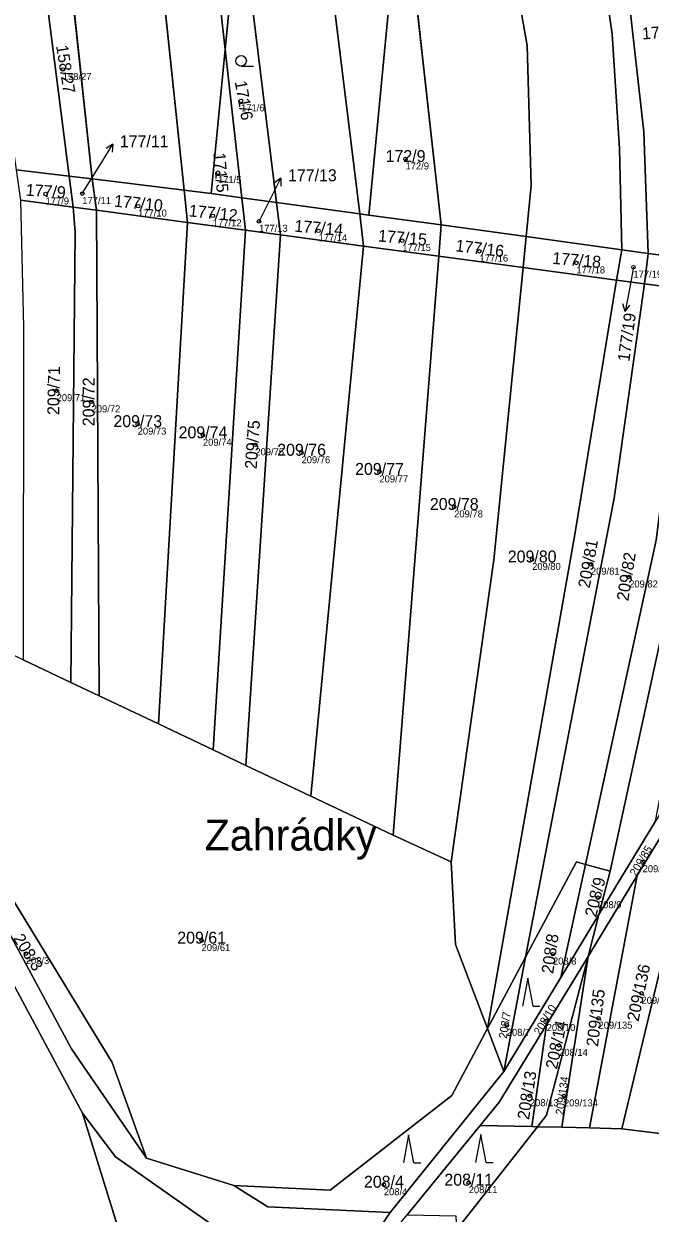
# Model space of a CAD drawing. Extents: x -603967 to -594699, y -1179315 to -1165625.
# Drawn here: x -597618.1 to -597528.8, y -1172909.2 to -1172739.7 of the extents above; entities that cross this region are included whole.
import ezdxf

# ---------------------------------------------------------------- set-up
doc = ezdxf.new("R2010")
doc.units = 0
for name, color, linetype in [('Definiční body', 7, 'Continuous'), ('Hranice parcel', 7, 'Continuous'), ('Parcelní čísla', 7, 'Continuous'), ('Polygon parcely', 7, 'Continuous'), ('Pop  PČ popisy', 7, 'Continuous'), ('Značky kultur', 7, 'Continuous')]:
    doc.layers.add(name, color=color, linetype=linetype)

msp = doc.modelspace()

# ---------------------------------------------------------------- linework, layer by layer
at = {"layer": 'Definiční body'}
for centre in [(-597612.53, -1172746.22994), (-597587.11, -1172750.68994), (-597563.66, -1172758.97994), (-597590.4, -1172760.92994), (-597614.99, -1172763.96994), (-597609.75, -1172763.90994), (-597601.79, -1172765.68994), (-597591.13, -1172767.07994), (-597584.55, -1172767.85994), (-597576.07, -1172769.19994), (-597564.13, -1172770.59994), (-597553.12, -1172772.11994), (-597539.29, -1172773.78994), (-597531.16, -1172774.38994), (-597613.41, -1172791.98994), (-597608.42, -1172793.57994), (-597601.85, -1172796.74994), (-597592.55, -1172798.33994), (-597585.07, -1172799.69994), (-597578.49, -1172800.82994), (-597567.38, -1172803.55994), (-597556.72, -1172808.54994), (-597545.61, -1172816.02994), (-597537.22, -1172816.70994), (-597531.77, -1172818.52994), (-597529.85, -1172859.09994), (-597536.21, -1172864.21994), (-597592.74, -1172870.32994), (-597617.81, -1172872.18994), (-597542.63, -1172872.24994), (-597530.01, -1172877.83994), (-597536.14, -1172881.38994), (-597549.22, -1172882.40994), (-597543.53, -1172881.72994), (-597541.76, -1172885.25994), (-597545.93, -1172892.42994), (-597541.06, -1172892.45994), (-597566.75, -1172905.10994), (-597554.65, -1172904.81994)]:
    msp.add_circle(centre, 0.25, dxfattribs=at)
at = {"layer": 'Hranice parcel'}
for p, q in [((-597570.19, -1172766.78), (-597579.38, -1172691.97)), ((-597589.37, -1172743.38), (-597594.18, -1172700.51)), ((-597595.22, -1172763.42), (-597601.41, -1172704.69)), ((-597613.71, -1172712.02), (-597608.32, -1172761.82)), ((-597611.6, -1172761.42), (-597617.67, -1172714.08)), ((-597568.89, -1172766.96), (-597564.18, -1172717.82)), ((-597558.57, -1172768.37), (-597564.18, -1172717.82)), ((-597589.37, -1172743.38), (-597587.32, -1172722.3)), ((-597582.05, -1172765.17), (-597587.32, -1172722.3)), ((-597591.36, -1172763.89), (-597589.37, -1172743.38)), ((-597587, -1172764.49), (-597589.37, -1172743.38)), ((-597619.16, -1172760.5), (-597611.6, -1172761.42)), ((-597611.03, -1172765.83), (-597611.6, -1172761.42)), ((-597611.6, -1172761.42), (-597608.32, -1172761.82)), ((-597608.32, -1172761.82), (-597607.73, -1172766.27)), ((-597608.32, -1172761.82), (-597595.22, -1172763.42)), ((-597594.74, -1172768.01), (-597595.22, -1172763.42)), ((-597595.22, -1172763.42), (-597591.36, -1172763.89)), ((-597591.36, -1172763.89), (-597587, -1172764.49)), ((-597618.55, -1172764.82), (-597611.03, -1172765.83)), ((-597611.03, -1172765.83), (-597607.73, -1172766.27)), ((-597587, -1172764.49), (-597582.05, -1172765.17)), ((-597586.48, -1172769.12), (-597587, -1172764.49)), ((-597582.05, -1172765.17), (-597570.19, -1172766.78)), ((-597581.48, -1172769.79), (-597582.05, -1172765.17)), ((-597607.73, -1172766.27), (-597594.74, -1172768.01)), ((-597607.36, -1172835.44), (-597607.73, -1172766.27)), ((-597570.19, -1172766.78), (-597568.89, -1172766.96)), ((-597569.63, -1172771.38), (-597570.19, -1172766.78)), ((-597568.89, -1172766.96), (-597558.57, -1172768.37)), ((-597598.88, -1172839.45), (-597594.74, -1172768.01)), ((-597594.74, -1172768.01), (-597586.48, -1172769.12)), ((-597591.11, -1172843.13), (-597586.48, -1172769.12)), ((-597586.48, -1172769.12), (-597581.48, -1172769.79)), ((-597558.92, -1172772.82), (-597558.57, -1172768.37)), ((-597558.57, -1172768.37), (-597546.46, -1172770.03)), ((-597586.41, -1172845.36), (-597581.48, -1172769.79)), ((-597581.48, -1172769.79), (-597569.63, -1172771.38)), ((-597546.89, -1172774.43), (-597546.46, -1172770.03)), ((-597546.46, -1172770.03), (-597532.83, -1172771.9)), ((-597577.14, -1172849.75), (-597569.63, -1172771.38)), ((-597569.63, -1172771.38), (-597558.92, -1172772.82)), ((-597533.55, -1172776.22), (-597532.83, -1172771.9)), ((-597532.83, -1172771.9), (-597529.06, -1172772.42)), ((-597529.57, -1172776.75), (-597529.06, -1172772.42)), ((-597529.06, -1172772.42), (-597522.87, -1172773.26)), ((-597565.41, -1172855.3), (-597558.92, -1172772.82)), ((-597558.92, -1172772.82), (-597546.89, -1172774.43)), ((-597546.89, -1172774.43), (-597533.55, -1172776.22)), ((-597533.55, -1172776.22), (-597529.57, -1172776.75)), ((-597529.57, -1172776.75), (-597523.41, -1172777.58)), ((-597611.38, -1172833.54), (-597618.17, -1172830.33)), ((-597607.36, -1172835.44), (-597611.38, -1172833.54)), ((-597598.88, -1172839.45), (-597607.36, -1172835.44)), ((-597591.11, -1172843.13), (-597598.88, -1172839.45)), ((-597586.41, -1172845.36), (-597591.11, -1172843.13)), ((-597577.14, -1172849.75), (-597586.41, -1172845.36)), ((-597530.61, -1172861.05), (-597520.68, -1172844.76)), ((-597565.41, -1172855.3), (-597577.14, -1172849.75)), ((-597536.07, -1172866.61), (-597528.03, -1172853.32)), ((-597557.14, -1172859.11), (-597565.41, -1172855.3)), ((-597541.5, -1172875.58), (-597537.99, -1172859.47)), ((-597534.46, -1172860.45), (-597537.99, -1172859.47)), ((-597536.07, -1172866.61), (-597534.46, -1172860.45)), ((-597537.63, -1172872.57), (-597530.61, -1172861.05)), ((-597537.43, -1172897.02), (-597530.61, -1172861.05)), ((-597541.5, -1172875.58), (-597536.07, -1172866.61)), ((-597537.63, -1172872.57), (-597536.07, -1172866.61)), ((-597546.53, -1172872.69), (-597551.96, -1172882.86)), ((-597549.62, -1172888.99), (-597546.53, -1172872.69)), ((-597543.57, -1172882.32), (-597537.63, -1172872.57)), ((-597541.36, -1172896.93), (-597537.63, -1172872.57)), ((-597549.62, -1172888.99), (-597541.5, -1172875.58)), ((-597549.62, -1172888.99), (-597551.96, -1172882.86)), ((-597545.64, -1172896.83), (-597543.57, -1172882.32)), ((-597565.86, -1172909.04), (-597549.62, -1172888.99)), ((-597609.7, -1172894.89), (-597599.63, -1172927.39)), ((-597563.42, -1172909.38), (-597553.01, -1172896.66)), ((-597556.37, -1172911.53), (-597544.84, -1172896.85)), ((-597545.64, -1172896.83), (-597553.01, -1172896.66)), ((-597544.84, -1172896.85), (-597545.64, -1172896.83)), ((-597541.36, -1172896.93), (-597544.84, -1172896.85)), ((-597537.43, -1172897.02), (-597541.36, -1172896.93)), ((-597532.79, -1172897.13), (-597537.43, -1172897.02)), ((-597524.24, -1172898.2), (-597532.79, -1172897.13)), ((-597588.14, -1172905.22), (-597600.57, -1172901.34)), ((-597571.27, -1172916.99), (-597565.86, -1172909.04))]:
    msp.add_line(p, q, dxfattribs=at)
for points in [[(-597529.06, -1172772.42), (-597529.67, -1172755.13), (-597533.92, -1172717.49), (-597537.73, -1172693.52), (-597542.15, -1172671.52)], [(-597532.83, -1172771.9), (-597533.15, -1172757.5), (-597534.21, -1172741.19), (-597538.43, -1172711.6), (-597545.49, -1172673.32)], [(-597546.46, -1172770.03), (-597545.76, -1172762.74), (-597546.31, -1172742.82), (-597555.17, -1172693.06), (-597557.04, -1172679.77)], [(-597611.38, -1172833.54), (-597610.76, -1172769.39), (-597611.03, -1172765.83)], [(-597557.14, -1172859.11), (-597551.05, -1172816.06), (-597546.89, -1172774.43)], [(-597551.96, -1172882.86), (-597539.49, -1172812.18), (-597533.55, -1172776.22)], [(-597546.53, -1172872.69), (-597533.9, -1172807.29), (-597529.57, -1172776.75)], [(-597537.99, -1172859.47), (-597527.91, -1172813.28), (-597523.41, -1172777.58)], [(-597534.46, -1172860.45), (-597523.22, -1172808.61), (-597518.36, -1172778.25)], [(-597600.57, -1172901.34), (-597605.51, -1172887.71), (-597645.57, -1172822.13), (-597649.68, -1172826.73)], [(-597650.17, -1172830.11), (-597634.48, -1172842.73), (-597611.3, -1172885.74), (-597600.57, -1172901.34)], [(-597650.63, -1172833.28), (-597638.01, -1172842.26), (-597609.7, -1172894.89)], [(-597532.79, -1172897.13), (-597523.17, -1172857.04), (-597520.68, -1172844.76)], [(-597551.96, -1172882.86), (-597556.53, -1172870.87), (-597557.14, -1172859.11)], [(-597537.99, -1172859.47), (-597539.27, -1172859.11), (-597546.53, -1172872.69)], [(-597544.84, -1172896.85), (-597543.55, -1172895.2), (-597537.63, -1172872.57)], [(-597551.96, -1172882.86), (-597557.05, -1172892.39), (-597574.38, -1172905.89), (-597588.14, -1172905.22)], [(-597553.01, -1172896.66), (-597550.3, -1172893.35), (-597543.57, -1172882.32)], [(-597578.6, -1172919.68), (-597605.03, -1172901.12), (-597609.7, -1172894.89)], [(-597588.14, -1172905.22), (-597583.31, -1172908.26), (-597565.86, -1172909.04)]]:
    msp.add_lwpolyline(points, dxfattribs=at)
at = {"layer": 'Polygon parcely'}
for points in [[(-597534.3, -1172667.32), (-597542.15, -1172671.52), (-597537.73, -1172693.52), (-597533.92, -1172717.49), (-597529.67, -1172755.13), (-597529.06, -1172772.42), (-597522.87, -1172773.26), (-597522.28, -1172768.57), (-597522.52, -1172739.46), (-597526.98, -1172708.75)], [(-597542.15, -1172671.52), (-597545.49, -1172673.32), (-597538.43, -1172711.6), (-597534.21, -1172741.19), (-597533.15, -1172757.5), (-597532.83, -1172771.9), (-597529.06, -1172772.42), (-597529.67, -1172755.13), (-597533.92, -1172717.49), (-597537.73, -1172693.52)], [(-597545.49, -1172673.32), (-597557.04, -1172679.77), (-597555.17, -1172693.06), (-597546.31, -1172742.82), (-597545.76, -1172762.74), (-597546.46, -1172770.03), (-597532.83, -1172771.9), (-597533.15, -1172757.5), (-597534.21, -1172741.19), (-597538.43, -1172711.6)], [(-597557.04, -1172679.77), (-597560.72, -1172681.78), (-597564.18, -1172717.82), (-597558.57, -1172768.37), (-597546.46, -1172770.03), (-597545.76, -1172762.74), (-597546.31, -1172742.82), (-597555.17, -1172693.06)], [(-597570.19, -1172766.78), (-597568.89, -1172766.96), (-597564.18, -1172717.82), (-597567.75, -1172685.61), (-597579.38, -1172691.97)], [(-597579.38, -1172691.97), (-597584.67, -1172695.02), (-597587.32, -1172722.3), (-597582.05, -1172765.17), (-597570.19, -1172766.78)], [(-597589.37, -1172743.38), (-597587.32, -1172722.3), (-597590.28, -1172698.26), (-597594.18, -1172700.51)], [(-597594.18, -1172700.51), (-597601.41, -1172704.69), (-597595.22, -1172763.42), (-597591.36, -1172763.89), (-597589.37, -1172743.38)], [(-597595.22, -1172763.42), (-597601.41, -1172704.69), (-597613.71, -1172712.02), (-597608.32, -1172761.82)], [(-597611.6, -1172761.42), (-597608.32, -1172761.82), (-597613.71, -1172712.02), (-597617.67, -1172714.08)], [(-597617.67, -1172714.08), (-597625.15, -1172718.4), (-597619.16, -1172760.5), (-597611.6, -1172761.42)], [(-597558.57, -1172768.37), (-597564.18, -1172717.82), (-597568.89, -1172766.96)], [(-597582.05, -1172765.17), (-597587.32, -1172722.3), (-597589.37, -1172743.38), (-597587, -1172764.49)], [(-597587, -1172764.49), (-597589.37, -1172743.38), (-597591.36, -1172763.89)], [(-597611.03, -1172765.83), (-597611.6, -1172761.42), (-597619.16, -1172760.5), (-597618.55, -1172764.82)], [(-597611.03, -1172765.83), (-597607.73, -1172766.27), (-597608.32, -1172761.82), (-597611.6, -1172761.42)], [(-597594.74, -1172768.01), (-597595.22, -1172763.42), (-597608.32, -1172761.82), (-597607.73, -1172766.27)], [(-597586.48, -1172769.12), (-597587, -1172764.49), (-597591.36, -1172763.89), (-597595.22, -1172763.42), (-597594.74, -1172768.01)], [(-597611.38, -1172833.54), (-597610.76, -1172769.39), (-597611.03, -1172765.83), (-597618.55, -1172764.82), (-597618.13, -1172782.99), (-597618.17, -1172830.33)], [(-597607.36, -1172835.44), (-597607.73, -1172766.27), (-597611.03, -1172765.83), (-597610.76, -1172769.39), (-597611.38, -1172833.54)], [(-597581.48, -1172769.79), (-597582.05, -1172765.17), (-597587, -1172764.49), (-597586.48, -1172769.12)], [(-597569.63, -1172771.38), (-597570.19, -1172766.78), (-597582.05, -1172765.17), (-597581.48, -1172769.79)], [(-597598.88, -1172839.45), (-597594.74, -1172768.01), (-597607.73, -1172766.27), (-597607.36, -1172835.44)], [(-597558.92, -1172772.82), (-597558.57, -1172768.37), (-597568.89, -1172766.96), (-597570.19, -1172766.78), (-597569.63, -1172771.38)], [(-597591.11, -1172843.13), (-597586.48, -1172769.12), (-597594.74, -1172768.01), (-597598.88, -1172839.45)], [(-597586.41, -1172845.36), (-597581.48, -1172769.79), (-597586.48, -1172769.12), (-597591.11, -1172843.13)], [(-597546.89, -1172774.43), (-597546.46, -1172770.03), (-597558.57, -1172768.37), (-597558.92, -1172772.82)], [(-597577.14, -1172849.75), (-597569.63, -1172771.38), (-597581.48, -1172769.79), (-597586.41, -1172845.36)], [(-597546.89, -1172774.43), (-597533.55, -1172776.22), (-597532.83, -1172771.9), (-597546.46, -1172770.03)], [(-597565.41, -1172855.3), (-597558.92, -1172772.82), (-597569.63, -1172771.38), (-597577.14, -1172849.75)], [(-597529.06, -1172772.42), (-597532.83, -1172771.9), (-597533.55, -1172776.22), (-597529.57, -1172776.75)], [(-597523.41, -1172777.58), (-597522.87, -1172773.26), (-597529.06, -1172772.42), (-597529.57, -1172776.75)], [(-597551.05, -1172816.06), (-597546.89, -1172774.43), (-597558.92, -1172772.82), (-597565.41, -1172855.3), (-597557.14, -1172859.11)], [(-597539.49, -1172812.18), (-597533.55, -1172776.22), (-597546.89, -1172774.43), (-597551.05, -1172816.06), (-597557.14, -1172859.11), (-597556.53, -1172870.87), (-597551.96, -1172882.86)], [(-597529.57, -1172776.75), (-597533.55, -1172776.22), (-597539.49, -1172812.18), (-597551.96, -1172882.86), (-597546.53, -1172872.69), (-597533.9, -1172807.29)], [(-597527.91, -1172813.28), (-597523.41, -1172777.58), (-597529.57, -1172776.75), (-597533.9, -1172807.29), (-597546.53, -1172872.69), (-597539.27, -1172859.11), (-597537.99, -1172859.47)], [(-597534.46, -1172860.45), (-597523.22, -1172808.61), (-597518.36, -1172778.25), (-597523.41, -1172777.58), (-597527.91, -1172813.28), (-597537.99, -1172859.47)], [(-597528.03, -1172853.32), (-597520.99, -1172816.83), (-597514.19, -1172778.81), (-597518.36, -1172778.25), (-597523.22, -1172808.61), (-597534.46, -1172860.45), (-597536.07, -1172866.61)], [(-597637.45, -1172821.21), (-597641.95, -1172819.08), (-597648.14, -1172816.15), (-597649.18, -1172823.26), (-597649.68, -1172826.73), (-597645.57, -1172822.13), (-597605.51, -1172887.71), (-597600.57, -1172901.34), (-597588.14, -1172905.22), (-597574.38, -1172905.89), (-597557.05, -1172892.39), (-597551.96, -1172882.86), (-597556.53, -1172870.87), (-597557.14, -1172859.11), (-597565.41, -1172855.3), (-597577.14, -1172849.75), (-597586.41, -1172845.36), (-597591.11, -1172843.13), (-597598.88, -1172839.45), (-597607.36, -1172835.44), (-597611.38, -1172833.54), (-597618.17, -1172830.33), (-597627.48, -1172825.93)], [(-597645.57, -1172822.13), (-597649.68, -1172826.73), (-597650.17, -1172830.11), (-597634.48, -1172842.73), (-597611.3, -1172885.74), (-597600.57, -1172901.34), (-597605.51, -1172887.71)], [(-597650.63, -1172833.28), (-597638.01, -1172842.26), (-597609.7, -1172894.89), (-597605.03, -1172901.12), (-597578.6, -1172919.68), (-597571.27, -1172916.99), (-597565.86, -1172909.04), (-597583.31, -1172908.26), (-597588.14, -1172905.22), (-597600.57, -1172901.34), (-597611.3, -1172885.74), (-597634.48, -1172842.73), (-597650.17, -1172830.11), (-597650.19, -1172830.23)], [(-597634.82, -1172941.98), (-597599.63, -1172927.39), (-597609.7, -1172894.89), (-597638.01, -1172842.26), (-597650.63, -1172833.28), (-597650.98, -1172835.68), (-597651.92, -1172842.12), (-597652.27, -1172844.56), (-597652.75, -1172847.85), (-597653.74, -1172854.63), (-597655.06, -1172863.69), (-597656.63, -1172874.7), (-597658.05, -1172886.36), (-597659.6, -1172899.14), (-597661.01, -1172910.7), (-597662.27, -1172921.05), (-597662.44, -1172931.04), (-597662.54, -1172938.91), (-597662.54, -1172947.84), (-597662.5, -1172951.67)], [(-597520.68, -1172844.76), (-597519.7, -1172841.11), (-597519.47, -1172839.39), (-597528.03, -1172853.32), (-597536.07, -1172866.61), (-597537.63, -1172872.57), (-597530.61, -1172861.05)], [(-597503.54, -1172844.31), (-597519.7, -1172841.11), (-597520.68, -1172844.76), (-597523.17, -1172857.04), (-597532.79, -1172897.13), (-597524.24, -1172898.2), (-597523.27, -1172895.86), (-597518, -1172883.14), (-597514.32, -1172874.25), (-597512.34, -1172869.47), (-597512.13, -1172868.86), (-597507.98, -1172856.67)], [(-597523.17, -1172857.04), (-597520.68, -1172844.76), (-597530.61, -1172861.05), (-597537.43, -1172897.02), (-597532.79, -1172897.13)], [(-597541.5, -1172875.58), (-597537.99, -1172859.47), (-597539.27, -1172859.11), (-597546.53, -1172872.69), (-597549.62, -1172888.99)], [(-597534.46, -1172860.45), (-597537.99, -1172859.47), (-597541.5, -1172875.58), (-597536.07, -1172866.61)], [(-597537.43, -1172897.02), (-597530.61, -1172861.05), (-597537.63, -1172872.57), (-597541.36, -1172896.93)], [(-597571.27, -1172916.99), (-597568.95, -1172916.14), (-597563.42, -1172909.38), (-597553.01, -1172896.66), (-597550.3, -1172893.35), (-597543.57, -1172882.32), (-597537.63, -1172872.57), (-597536.07, -1172866.61), (-597541.5, -1172875.58), (-597549.62, -1172888.99), (-597565.86, -1172909.04)], [(-597549.62, -1172888.99), (-597546.53, -1172872.69), (-597551.96, -1172882.86)], [(-597543.55, -1172895.2), (-597537.63, -1172872.57), (-597543.57, -1172882.32), (-597545.64, -1172896.83), (-597544.84, -1172896.85)], [(-597541.36, -1172896.93), (-597537.63, -1172872.57), (-597543.55, -1172895.2), (-597544.84, -1172896.85)], [(-597574.38, -1172905.89), (-597588.14, -1172905.22), (-597583.31, -1172908.26), (-597565.86, -1172909.04), (-597549.62, -1172888.99), (-597551.96, -1172882.86), (-597557.05, -1172892.39)], [(-597545.64, -1172896.83), (-597543.57, -1172882.32), (-597550.3, -1172893.35), (-597553.01, -1172896.66)], [(-597578.6, -1172919.68), (-597605.03, -1172901.12), (-597609.7, -1172894.89), (-597599.63, -1172927.39)], [(-597563.42, -1172909.38), (-597556.49, -1172909.56), (-597556.37, -1172911.53), (-597544.84, -1172896.85), (-597545.64, -1172896.83), (-597553.01, -1172896.66)]]:
    msp.add_lwpolyline(points, close=True, dxfattribs=at)
msp.add_lwpolyline([(-597524.24, -1172898.2), (-597532.79, -1172897.13), (-597537.43, -1172897.02), (-597541.36, -1172896.93), (-597544.84, -1172896.85), (-597556.37, -1172911.53), (-597555.58, -1172919.7), (-597555.24, -1172923.28), (-597554.53, -1172930.65), (-597554.01, -1172936.13), (-597553.2, -1172944.57), (-597552.82, -1172948.48), (-597551.74, -1172959.75), (-597551.1, -1172966.42), (-597544.54, -1172977.54), (-597534.65, -1173013.07), (-597530.67, -1173005.87), (-597522.51, -1173006.81)], dxfattribs=at)
at = {"layer": 'Pop  PČ popisy'}
for p, q in [((-597606.98, -1172759.43), (-597605.39, -1172756.885)), ((-597605.39, -1172756.885), (-597606.345, -1172757.469)), ((-597605.39, -1172756.885), (-597605.496, -1172758)), ((-597609.75, -1172763.91), (-597606.98, -1172759.43)), ((-597582.78, -1172764.39), (-597581.418, -1172761.716)), ((-597581.418, -1172761.716), (-597582.318, -1172762.381)), ((-597581.418, -1172761.716), (-597581.426, -1172762.836)), ((-597584.55, -1172767.86), (-597582.78, -1172764.39)), ((-597531.16, -1172774.39), (-597531.78, -1172777.75)), ((-597531.78, -1172777.75), (-597532.353, -1172780.696)), ((-597532.353, -1172780.696), (-597532.653, -1172779.617)), ((-597532.353, -1172780.696), (-597531.67, -1172779.808))]:
    msp.add_line(p, q, dxfattribs=at)
at = {"layer": 'Značky kultur'}
for p, q in [((-597587.103, -1172745.74), (-597585.353, -1172745.74)), ((-597546.23, -1172875.68), (-597546.98, -1172879.68)), ((-597545.48, -1172879.68), (-597546.23, -1172875.68)), ((-597545.48, -1172879.68), (-597544.484, -1172879.68)), ((-597563.21, -1172898.01), (-597563.96, -1172902.01)), ((-597562.46, -1172902.01), (-597563.21, -1172898.01)), ((-597552.93, -1172897.94), (-597553.68, -1172901.94)), ((-597552.18, -1172901.94), (-597552.93, -1172897.94)), ((-597562.46, -1172902.01), (-597561.464, -1172902.01)), ((-597552.18, -1172901.94), (-597551.184, -1172901.94))]:
    msp.add_line(p, q, dxfattribs=at)
msp.add_circle((-597587.10286, -1172744.98981), 0.75, dxfattribs=at)

# ---------------------------------------------------------------- texts
at = {"layer": 'Definiční body'}
for s, p in [('158/27', (-597612.53, -1172747.719)), ('171/6', (-597587.11, -1172752.179)), ('172/9', (-597563.66, -1172760.469)), ('171/5', (-597590.4, -1172762.419)), ('177/11', (-597609.75, -1172765.399)), ('177/9', (-597614.99, -1172765.459)), ('177/10', (-597601.79, -1172767.179)), ('177/12', (-597591.13, -1172768.569)), ('177/13', (-597584.55, -1172769.349)), ('177/14', (-597576.07, -1172770.689)), ('177/15', (-597564.13, -1172772.089)), ('177/16', (-597553.12, -1172773.609)), ('177/18', (-597539.29, -1172775.279)), ('177/19', (-597531.16, -1172775.879)), ('209/71', (-597613.41, -1172793.479)), ('209/72', (-597608.42, -1172795.069)), ('209/73', (-597601.85, -1172798.239)), ('209/74', (-597592.55, -1172799.829)), ('209/75', (-597585.07, -1172801.189)), ('209/76', (-597578.49, -1172802.319)), ('209/77', (-597567.38, -1172805.049)), ('209/78', (-597556.72, -1172810.039)), ('209/80', (-597545.61, -1172817.519)), ('209/81', (-597537.22, -1172818.199)), ('209/82', (-597531.77, -1172820.019)), ('209/85', (-597529.85, -1172860.589)), ('208/9', (-597536.21, -1172865.709)), ('209/61', (-597592.74, -1172871.819)), ('208/3', (-597617.81, -1172873.679)), ('208/8', (-597542.63, -1172873.739)), ('209/136', (-597530.01, -1172879.329)), ('208/7', (-597549.22, -1172883.899)), ('208/10', (-597543.53, -1172883.219)), ('209/135', (-597536.14, -1172882.879)), ('208/14', (-597541.76, -1172886.749)), ('208/13', (-597545.93, -1172893.919)), ('209/134', (-597541.06, -1172893.949)), ('208/4', (-597566.75, -1172906.599)), ('208/11', (-597554.65, -1172906.309))]:
    msp.add_text(s, height=0.999996, dxfattribs=at).set_placement(p)
at = {"layer": 'Parcelní čísla'}
for s, height, rotation, p in [('172/14', 1.699998, 4, (-597529.888, -1172741.955)), ('158/27', 1.699998, 279, (-597613.492, -1172742.872)), ('171/6', 1.699998, 280, (-597588.021, -1172747.97)), ('171/5', 1.699998, 275, (-597591.07, -1172758.141)), ('177/9', 1.699998, 356, (-597617.848, -1172764.196)), ('177/10', 1.699998, 354, (-597605.281, -1172765.75)), ('177/12', 1.699998, 354, (-597594.621, -1172767.14)), ('177/14', 1.699998, 355, (-597579.56, -1172769.321)), ('177/15', 1.699998, 355, (-597567.62, -1172770.721)), ('177/16', 1.699998, 353, (-597556.612, -1172772.119)), ('177/18', 1.699998, 355, (-597542.78, -1172773.911)), ('177/19', 1.699998, 82, (-597531.754, -1172787.922)), ('209/71', 1.699998, 89, (-597613.045, -1172795.463)), ('209/72', 1.699998, 90, (-597607.995, -1172797.046)), ('209/75', 1.699998, 86, (-597584.887, -1172803.187)), ('209/81', 1.699998, 80, (-597537.403, -1172820.197)), ('209/82', 1.699998, 81, (-597531.892, -1172822.02)), ('209/85', 1.14, 59, (-597530.802, -1172861.239)), ('208/9', 1.699998, 76, (-597536.483, -1172867.074)), ('208/3', 1.699998, 302, (-597619.673, -1172870.01)), ('208/8', 1.699998, 82, (-597542.603, -1172875.117)), ('209/136', 1.699998, 78, (-597530.446, -1172881.935)), ('209/135', 1.699998, 83, (-597536.217, -1172885.507)), ('208/10', 1.14, 59, (-597544.482, -1172883.869)), ('208/7', 1.14, 81, (-597549.236, -1172884.333)), ('208/14', 1.699998, 78, (-597542.064, -1172888.739)), ('208/13', 1.699998, 81, (-597546.052, -1172895.92)), ('209/134', 1.14, 82, (-597541.16, -1172895.22))]:
    msp.add_text(s, height=height, rotation=rotation, dxfattribs=at).set_placement(p)
for s, p in [('177/11', (-597604.4, -1172757.305)), ('172/9', (-597566.496, -1172759.405)), ('177/13', (-597580.42, -1172762.145)), ('209/73', (-597605.316, -1172797.175)), ('209/74', (-597596.016, -1172798.765)), ('209/76', (-597581.956, -1172801.255)), ('209/77', (-597570.846, -1172803.985)), ('209/78', (-597560.186, -1172808.975)), ('209/80', (-597549.076, -1172816.455)), ('209/61', (-597596.206, -1172870.755)), ('208/4', (-597569.586, -1172905.535)), ('208/11', (-597558.116, -1172905.245))]:
    msp.add_text(s, height=1.699998, dxfattribs=at).set_placement(p)
at = {"layer": 'Pop  PČ popisy'}
msp.add_text('Zahrádky', height=4.399998, dxfattribs=at).set_placement((-597592.317, -1172857.49))

doc.saveas('drawing.dxf')
